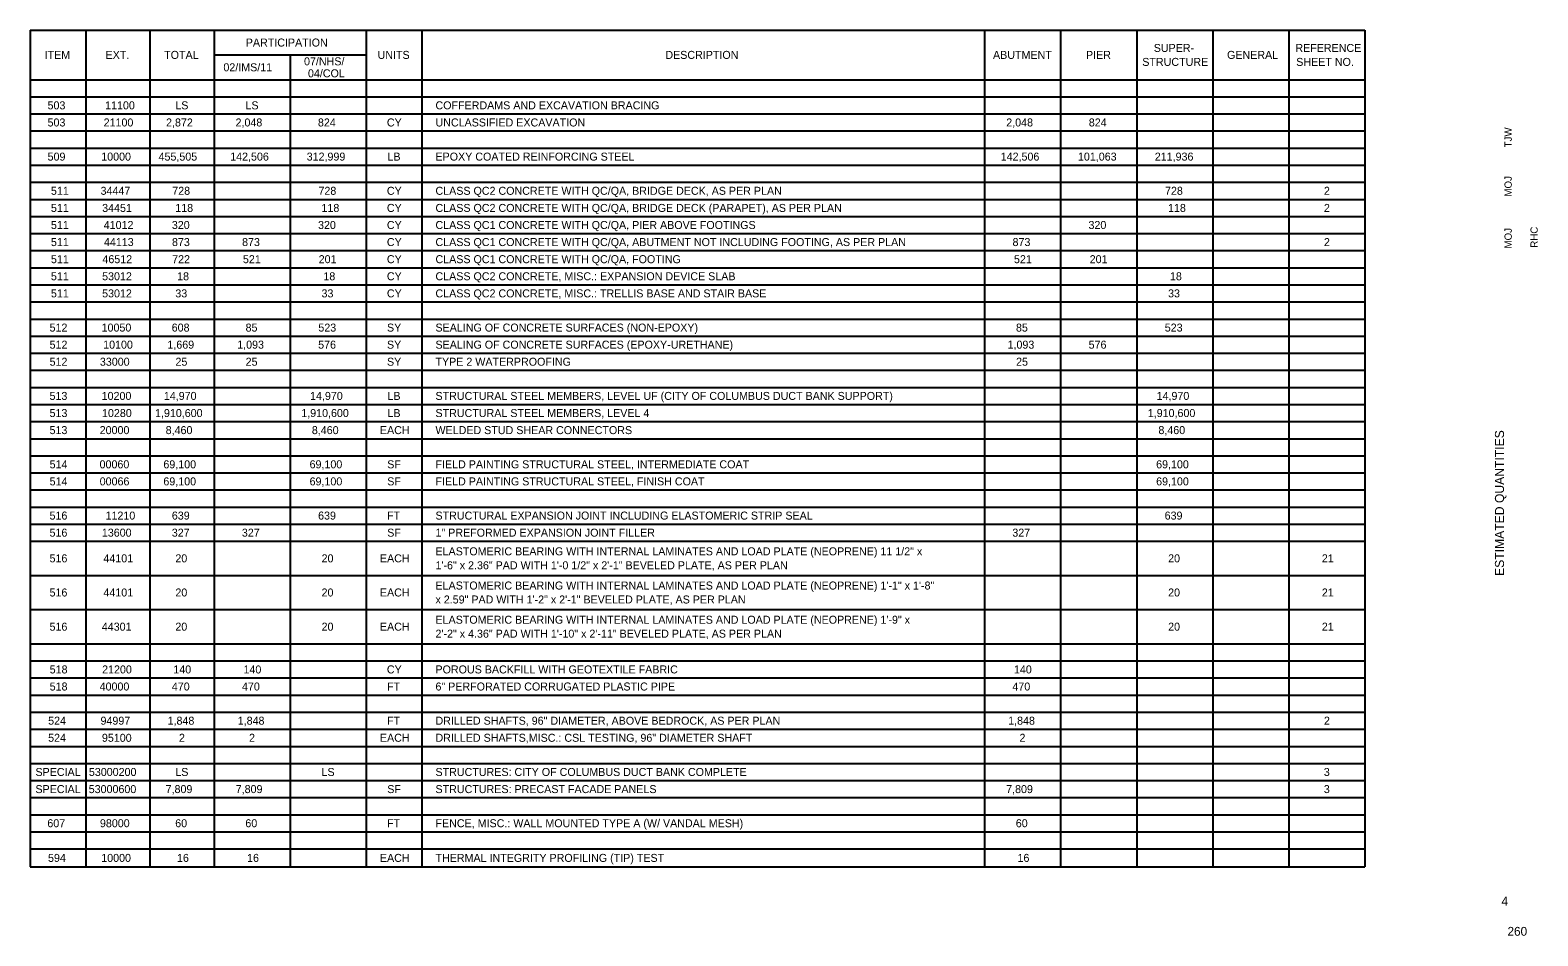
# Model space of a CAD drawing. Extents: x 4.4 to 33.4, y 1.1 to 18.5.
import ezdxf

# ---------------------------------------------------------------- set-up
doc = ezdxf.new("R2010")
doc.units = 0
doc.layers.add('BR_P_Gen_Text', color=7, linetype='Continuous')
doc.layers.add('BR_X_Slab_Object', color=7, linetype='Continuous')

msp = doc.modelspace()

# ---------------------------------------------------------------- linework, layer by layer
at = {"layer": 'BR_P_Gen_Text'}
for p, q in [((4.365, 18.537), (30.075, 18.537)), ((4.365, 18.537), (4.365, 17.582)), ((5.435, 18.537), (5.435, 2.413)), ((6.671, 18.537), (6.671, 2.413)), ((7.906, 18.537), (7.906, 2.413)), ((10.838, 18.537), (10.838, 2.413)), ((11.908, 18.537), (11.908, 2.413)), ((22.746, 18.537), (22.746, 2.413)), ((24.212, 18.537), (24.212, 2.413)), ((25.678, 18.537), (25.678, 2.413)), ((27.144, 18.537), (27.144, 2.413)), ((28.61, 18.537), (28.61, 2.413)), ((30.075, 18.537), (30.075, 17.582)), ((7.906, 18.06), (10.838, 18.06)), ((9.372, 18.06), (9.372, 2.413)), ((4.365, 17.582), (30.075, 17.582)), ((4.365, 17.582), (4.365, 2.413)), ((30.075, 17.582), (30.075, 2.413)), ((4.365, 17.253), (30.075, 17.253)), ((4.365, 16.923), (30.075, 16.923)), ((4.365, 16.594), (30.075, 16.594)), ((4.365, 16.264), (30.075, 16.264)), ((4.365, 15.935), (30.075, 15.935)), ((4.365, 15.605), (30.075, 15.605)), ((4.365, 15.276), (30.075, 15.276)), ((4.365, 14.947), (30.075, 14.947)), ((4.365, 14.617), (30.075, 14.617)), ((4.365, 14.288), (30.075, 14.288)), ((4.365, 13.958), (30.075, 13.958)), ((4.365, 13.629), (30.075, 13.629)), ((4.365, 13.3), (30.075, 13.3)), ((4.365, 12.97), (30.075, 12.97)), ((4.365, 12.641), (30.075, 12.641)), ((4.365, 12.311), (30.075, 12.311)), ((4.365, 11.982), (30.075, 11.982)), ((4.365, 11.653), (30.075, 11.653)), ((4.365, 11.323), (30.075, 11.323)), ((4.365, 10.994), (30.075, 10.994)), ((4.365, 10.664), (30.075, 10.664)), ((4.365, 10.335), (30.075, 10.335)), ((4.365, 10.005), (30.075, 10.005)), ((4.365, 9.676), (30.075, 9.676)), ((4.365, 9.347), (30.075, 9.347)), ((4.365, 9.017), (30.075, 9.017)), ((4.365, 8.688), (30.075, 8.688)), ((4.365, 8.029), (30.075, 8.029)), ((4.365, 7.37), (30.075, 7.37)), ((4.365, 6.711), (30.075, 6.711)), ((4.365, 6.382), (30.075, 6.382)), ((4.365, 6.053), (30.075, 6.053)), ((4.365, 5.723), (30.075, 5.723)), ((4.365, 5.394), (30.075, 5.394)), ((4.365, 5.064), (30.075, 5.064)), ((4.365, 4.735), (30.075, 4.735)), ((4.365, 4.405), (30.075, 4.405)), ((4.365, 4.076), (30.075, 4.076)), ((4.365, 3.747), (30.075, 3.747)), ((4.365, 3.417), (30.075, 3.417)), ((4.365, 3.088), (30.075, 3.088)), ((4.365, 2.758), (30.075, 2.758)), ((4.365, 2.413), (30.075, 2.413))]:
    msp.add_line(p, q, dxfattribs=at)

# ---------------------------------------------------------------- texts
for s, height, p in [('PARTICIPATION', 0.154, (8.518, 18.221)), ('ITEM', 0.154, (4.643, 17.983)), ('EXT.', 0.154, (5.817, 17.983)), ('TOTAL', 0.154, (6.946, 17.983)), ('07/NHS/', 0.154, (9.64, 17.859)), ('UNITS', 0.154, (11.057, 17.983)), ('DESCRIPTION', 0.154, (16.6, 17.983)), ('ABUTMENT', 0.154, (22.911, 17.983)), ('PIER', 0.154, (24.702, 17.983)), ('SUPER-', 0.154, (26.007, 18.117)), ('GENERAL', 0.154, (27.419, 17.983)), ('REFERENCE', 0.154, (28.735, 18.117)), ('02/IMS/11', 0.154, (8.087, 17.744)), ('04/COL', 0.154, (9.716, 17.628)), ('STRUCTURE', 0.154, (25.786, 17.848)), ('SHEET NO.', 0.154, (28.751, 17.848)), ('503', 0.154, (4.7, 17.011)), ('11100', 0.154, (5.809, 17.011)), ('LS', 0.154, (7.161, 17.011)), ('LS', 0.154, (8.512, 17.011)), ('COFFERDAMS AND EXCAVATION BRACING', 0.154, (12.172, 17.011)), ('503', 0.154, (4.7, 16.681)), ('21100', 0.154, (5.78, 16.681)), ('2,872', 0.154, (6.983, 16.681)), ('2,048', 0.154, (8.321, 16.681)), ('824', 0.154, (9.908, 16.681)), ('CY', 0.154, (11.236, 16.681)), ('UNCLASSIFIED EXCAVATION', 0.154, (12.172, 16.681)), ('2,048', 0.154, (23.166, 16.681)), ('824', 0.154, (24.756, 16.681)), ('509', 0.154, (4.701, 16.023)), ('10000', 0.154, (5.734, 16.023)), ('455,505', 0.154, (6.838, 16.023)), ('142,506', 0.154, (8.218, 16.023)), ('312,999', 0.154, (9.691, 16.023)), ('LB', 0.154, (11.247, 16.023)), ('EPOXY COATED REINFORCING STEEL', 0.154, (12.172, 16.023)), ('142,506', 0.154, (23.059, 16.023)), ('101,063', 0.154, (24.547, 16.023)), ('211,936', 0.154, (26.027, 16.023)), ('511', 0.154, (4.765, 15.364)), ('34447', 0.154, (5.721, 15.364)), ('728', 0.154, (7.102, 15.364)), ('728', 0.154, (9.918, 15.364)), ('CY', 0.154, (11.236, 15.364)), ('CLASS QC2 CONCRETE WITH QC/QA, BRIDGE DECK, AS PER PLAN', 0.154, (12.172, 15.364)), ('728', 0.154, (26.224, 15.364)), ('2', 0.154, (29.285, 15.364)), ('511', 0.154, (4.765, 15.034)), ('34451', 0.154, (5.752, 15.034)), ('118', 0.154, (7.16, 15.034)), ('118', 0.154, (9.976, 15.034)), ('CY', 0.154, (11.236, 15.034)), ('CLASS QC2 CONCRETE WITH QC/QA, BRIDGE DECK (PARAPET), AS PER PLAN', 0.154, (12.172, 15.034)), ('118', 0.154, (26.282, 15.034)), ('2', 0.154, (29.285, 15.034)), ('511', 0.154, (4.765, 14.705)), ('41012', 0.154, (5.782, 14.705)), ('320', 0.154, (7.094, 14.705)), ('320', 0.154, (9.91, 14.705)), ('CY', 0.154, (11.236, 14.705)), ('CLASS QC1 CONCRETE WITH QC/QA, PIER ABOVE FOOTINGS', 0.154, (12.172, 14.705)), ('320', 0.154, (24.75, 14.705)), ('511', 0.154, (4.765, 14.376)), ('44113', 0.154, (5.786, 14.376)), ('873', 0.154, (7.097, 14.376)), ('873', 0.154, (8.447, 14.376)), ('CY', 0.154, (11.236, 14.376)), ('CLASS QC1 CONCRETE WITH QC/QA, ABUTMENT NOT INCLUDING FOOTING, AS PER PLAN', 0.154, (12.172, 14.376)), ('873', 0.154, (23.287, 14.376)), ('2', 0.154, (29.285, 14.376)), ('511', 0.154, (4.765, 14.046)), ('46512', 0.154, (5.757, 14.046)), ('722', 0.154, (7.1, 14.046)), ('521', 0.154, (8.463, 14.046)), ('201', 0.154, (9.922, 14.046)), ('CY', 0.154, (11.236, 14.046)), ('CLASS QC1 CONCRETE WITH QC/QA, FOOTING', 0.154, (12.172, 14.046)), ('521', 0.154, (23.315, 14.046)), ('201', 0.154, (24.773, 14.046)), ('511', 0.154, (4.765, 13.717)), ('53012', 0.154, (5.751, 13.717)), ('18', 0.154, (7.196, 13.717)), ('18', 0.154, (10.013, 13.717)), ('CY', 0.154, (11.236, 13.717)), ('CLASS QC2 CONCRETE, MISC.: EXPANSION DEVICE SLAB', 0.154, (12.172, 13.717)), ('18', 0.154, (26.319, 13.717)), ('511', 0.154, (4.765, 13.387)), ('53012', 0.154, (5.751, 13.387)), ('33', 0.154, (7.161, 13.387)), ('33', 0.154, (9.977, 13.387)), ('CY', 0.154, (11.236, 13.387)), ('CLASS QC2 CONCRETE, MISC.: TRELLIS BASE AND STAIR BASE', 0.154, (12.172, 13.387)), ('33', 0.154, (26.283, 13.387)), ('512', 0.154, (4.739, 12.728)), ('10050', 0.154, (5.741, 12.728)), ('608', 0.154, (7.091, 12.728)), ('85', 0.154, (8.514, 12.728)), ('523', 0.154, (9.916, 12.728)), ('SY', 0.154, (11.238, 12.728)), ('SEALING OF CONCRETE SURFACES (NON-EPOXY)', 0.154, (12.172, 12.728)), ('85', 0.154, (23.353, 12.728)), ('523', 0.154, (26.219, 12.728)), ('512', 0.154, (4.739, 12.399)), ('10100', 0.154, (5.771, 12.399)), ('1,669', 0.154, (7.008, 12.399)), ('1,093', 0.154, (8.353, 12.399)), ('576', 0.154, (9.912, 12.399)), ('SY', 0.154, (11.238, 12.399)), ('SEALING OF CONCRETE SURFACES (EPOXY-URETHANE)', 0.154, (12.172, 12.399)), ('1,093', 0.154, (23.191, 12.399)), ('576', 0.154, (24.753, 12.399)), ('512', 0.154, (4.739, 12.07)), ('33000', 0.154, (5.708, 12.07)), ('25', 0.154, (7.164, 12.07)), ('25', 0.154, (8.515, 12.07)), ('SY', 0.154, (11.238, 12.07)), ('TYPE 2 WATERPROOFING', 0.154, (12.172, 12.07)), ('25', 0.154, (23.355, 12.07)), ('513', 0.154, (4.738, 11.411)), ('10200', 0.154, (5.742, 11.411)), ('14,970', 0.154, (6.94, 11.411)), ('14,970', 0.154, (9.756, 11.411)), ('LB', 0.154, (11.247, 11.411)), ('STRUCTURAL STEEL MEMBERS, LEVEL UF (CITY OF COLUMBUS DUCT BANK SUPPORT)', 0.154, (12.172, 11.411)), ('14,970', 0.154, (26.062, 11.411)), ('513', 0.154, (4.738, 11.081)), ('10280', 0.154, (5.749, 11.081)), ('1,910,600', 0.154, (6.77, 11.081)), ('1,910,600', 0.154, (9.587, 11.081)), ('LB', 0.154, (11.247, 11.081)), ('STRUCTURAL STEEL MEMBERS, LEVEL 4', 0.154, (12.172, 11.081)), ('1,910,600', 0.154, (25.892, 11.081)), ('513', 0.154, (4.738, 10.752)), ('20000', 0.154, (5.704, 10.752)), ('8,460', 0.154, (6.975, 10.752)), ('8,460', 0.154, (9.791, 10.752)), ('EACH', 0.154, (11.102, 10.752)), ('WELDED STUD SHEAR CONNECTORS', 0.154, (12.172, 10.752)), ('8,460', 0.154, (26.097, 10.752)), ('514', 0.154, (4.74, 10.093)), ('00060', 0.154, (5.702, 10.093)), ('69,100', 0.154, (6.931, 10.093)), ('69,100', 0.154, (9.747, 10.093)), ('SF', 0.154, (11.243, 10.093)), ('FIELD PAINTING STRUCTURAL STEEL, INTERMEDIATE COAT', 0.154, (12.172, 10.093)), ('69,100', 0.154, (26.053, 10.093)), ('514', 0.154, (4.74, 9.764)), ('00066', 0.154, (5.704, 9.764)), ('69,100', 0.154, (6.931, 9.764)), ('69,100', 0.154, (9.747, 9.764)), ('SF', 0.154, (11.243, 9.764)), ('FIELD PAINTING STRUCTURAL STEEL, FINISH COAT', 0.154, (12.172, 9.764)), ('69,100', 0.154, (26.053, 9.764)), ('516', 0.154, (4.738, 9.105)), ('11210', 0.154, (5.817, 9.105)), ('639', 0.154, (7.094, 9.105)), ('639', 0.154, (9.911, 9.105)), ('FT', 0.154, (11.238, 9.105)), ('STRUCTURAL EXPANSION JOINT INCLUDING ELASTOMERIC STRIP SEAL ', 0.154, (12.172, 9.105)), ('639', 0.154, (26.217, 9.105)), ('516', 0.154, (4.738, 8.776)), ('13600', 0.154, (5.746, 8.776)), ('327', 0.154, (7.093, 8.776)), ('327', 0.154, (8.443, 8.776)), ('SF', 0.154, (11.243, 8.776)), ('1" PREFORMED EXPANSION JOINT FILLER', 0.154, (12.172, 8.776)), ('327', 0.154, (23.283, 8.776)), ('516', 0.154, (4.738, 8.281)), ('44101', 0.154, (5.776, 8.281)), ('20', 0.154, (7.162, 8.281)), ('20', 0.154, (9.978, 8.281)), ('EACH', 0.154, (11.102, 8.281)), ('ELASTOMERIC BEARING WITH INTERNAL LAMINATES AND LOAD PLATE (NEOPRENE) 11 1/2" x', 0.154, (12.172, 8.416)), ('20', 0.154, (26.284, 8.281)), ('21', 0.154, (29.245, 8.281)), ('1\'-6" x 2.36" PAD WITH 1\'-0 1/2" x 2\'-1" BEVELED PLATE, AS PER PLAN', 0.154, (12.172, 8.147)), ('ELASTOMERIC BEARING WITH INTERNAL LAMINATES AND LOAD PLATE (NEOPRENE) 1\'-1" x 1\'-8"', 0.154, (12.172, 7.757)), ('516', 0.154, (4.738, 7.623)), ('44101', 0.154, (5.776, 7.623)), ('20', 0.154, (7.162, 7.623)), ('20', 0.154, (9.978, 7.623)), ('EACH', 0.154, (11.102, 7.623)), ('x 2.59" PAD WITH 1\'-2" x 2\'-1" BEVELED PLATE, AS PER PLAN', 0.154, (12.172, 7.488)), ('20', 0.154, (26.284, 7.623)), ('21', 0.154, (29.245, 7.623)), ('ELASTOMERIC BEARING WITH INTERNAL LAMINATES AND LOAD PLATE (NEOPRENE) 1\'-9" x', 0.154, (12.172, 7.098)), ('516', 0.154, (4.738, 6.964)), ('44301', 0.154, (5.745, 6.964)), ('20', 0.154, (7.162, 6.964)), ('20', 0.154, (9.978, 6.964)), ('EACH', 0.154, (11.102, 6.964)), ('2\'-2" x 4.36" PAD WITH 1\'-10" x 2\'-11" BEVELED PLATE, AS PER PLAN', 0.154, (12.172, 6.829)), ('20', 0.154, (26.284, 6.964)), ('21', 0.154, (29.245, 6.964)), ('518', 0.154, (4.741, 6.14)), ('21200', 0.154, (5.751, 6.14)), ('140', 0.154, (7.123, 6.14)), ('140', 0.154, (8.474, 6.14)), ('CY', 0.154, (11.236, 6.14)), ('POROUS BACKFILL WITH GEOTEXTILE FABRIC', 0.154, (12.172, 6.14)), ('140', 0.154, (23.314, 6.14)), ('518', 0.154, (4.741, 5.811)), ('40000', 0.154, (5.703, 5.811)), ('470', 0.154, (7.094, 5.811)), ('470', 0.154, (8.445, 5.811)), ('FT', 0.154, (11.238, 5.811)), ('6" PERFORATED CORRUGATED PLASTIC PIPE', 0.154, (12.172, 5.811)), ('470', 0.154, (23.285, 5.811)), ('524', 0.154, (4.711, 5.152)), ('94997', 0.154, (5.72, 5.152)), ('1,848', 0.154, (7.012, 5.152)), ('1,848', 0.154, (8.363, 5.152)), ('FT', 0.154, (11.238, 5.152)), ('DRILLED SHAFTS, 96" DIAMETER, ABOVE BEDROCK, AS PER PLAN', 0.154, (12.172, 5.152)), ('1,848', 0.154, (23.203, 5.152)), ('2', 0.154, (29.285, 5.152)), ('524', 0.154, (4.711, 4.823)), ('95100', 0.154, (5.747, 4.823)), ('2', 0.154, (7.231, 4.823)), ('2', 0.154, (8.581, 4.823)), ('EACH', 0.154, (11.102, 4.823)), ('DRILLED SHAFTS,MISC.: CSL TESTING, 96" DIAMETER SHAFT', 0.154, (12.172, 4.823)), ('2', 0.154, (23.421, 4.823)), ('SPECIAL', 0.154, (4.467, 4.164)), ('53000200', 0.154, (5.496, 4.164)), ('LS', 0.154, (7.161, 4.164)), ('LS', 0.154, (9.977, 4.164)), ('STRUCTURES: CITY OF COLUMBUS DUCT BANK COMPLETE', 0.154, (12.172, 4.164)), ('3', 0.154, (29.283, 4.164)), ('SPECIAL', 0.154, (4.467, 3.834)), ('53000600', 0.154, (5.493, 3.834)), ('7,809', 0.154, (6.974, 3.834)), ('7,809', 0.154, (8.324, 3.834)), ('SF', 0.154, (11.243, 3.834)), ('STRUCTURES: PRECAST FACADE PANELS', 0.154, (12.172, 3.834)), ('7,809', 0.154, (23.164, 3.834)), ('3', 0.154, (29.283, 3.834)), ('607', 0.154, (4.696, 3.176)), ('98000', 0.154, (5.709, 3.176)), ('60', 0.154, (7.159, 3.176)), ('60', 0.154, (8.51, 3.176)), ('FT', 0.154, (11.238, 3.176)), ('FENCE, MISC.: WALL MOUNTED TYPE A (W/ VANDAL MESH)', 0.154, (12.172, 3.176)), ('60', 0.154, (23.35, 3.176)), ('594', 0.154, (4.709, 2.508)), ('10000', 0.154, (5.734, 2.508)), ('16', 0.154, (7.193, 2.508)), ('16', 0.154, (8.543, 2.508)), ('EACH', 0.154, (11.102, 2.508)), ('THERMAL INTEGRITY PROFILING (TIP) TEST', 0.154, (12.172, 2.508)), ('16', 0.154, (23.383, 2.508)), ('4', 0.17, (32.704, 1.665)), ('260', 0.17, (32.82, 1.085))]:
    msp.add_text(s, height=height, dxfattribs=at).set_placement(p)
at = {"layer": 'BR_X_Slab_Object'}
for s, height, p in [('TJW', 0.14, (32.903, 16.278)), ('MOJ', 0.14, (32.903, 15.329)), ('MOJ', 0.14, (32.903, 14.329)), ('RHC', 0.14, (33.403, 14.344)), ('ESTIMATED QUANTITIES', 0.175, (32.754, 8.019))]:
    msp.add_text(s, height=height, rotation=90, dxfattribs=at).set_placement(p)

doc.saveas('drawing.dxf')
